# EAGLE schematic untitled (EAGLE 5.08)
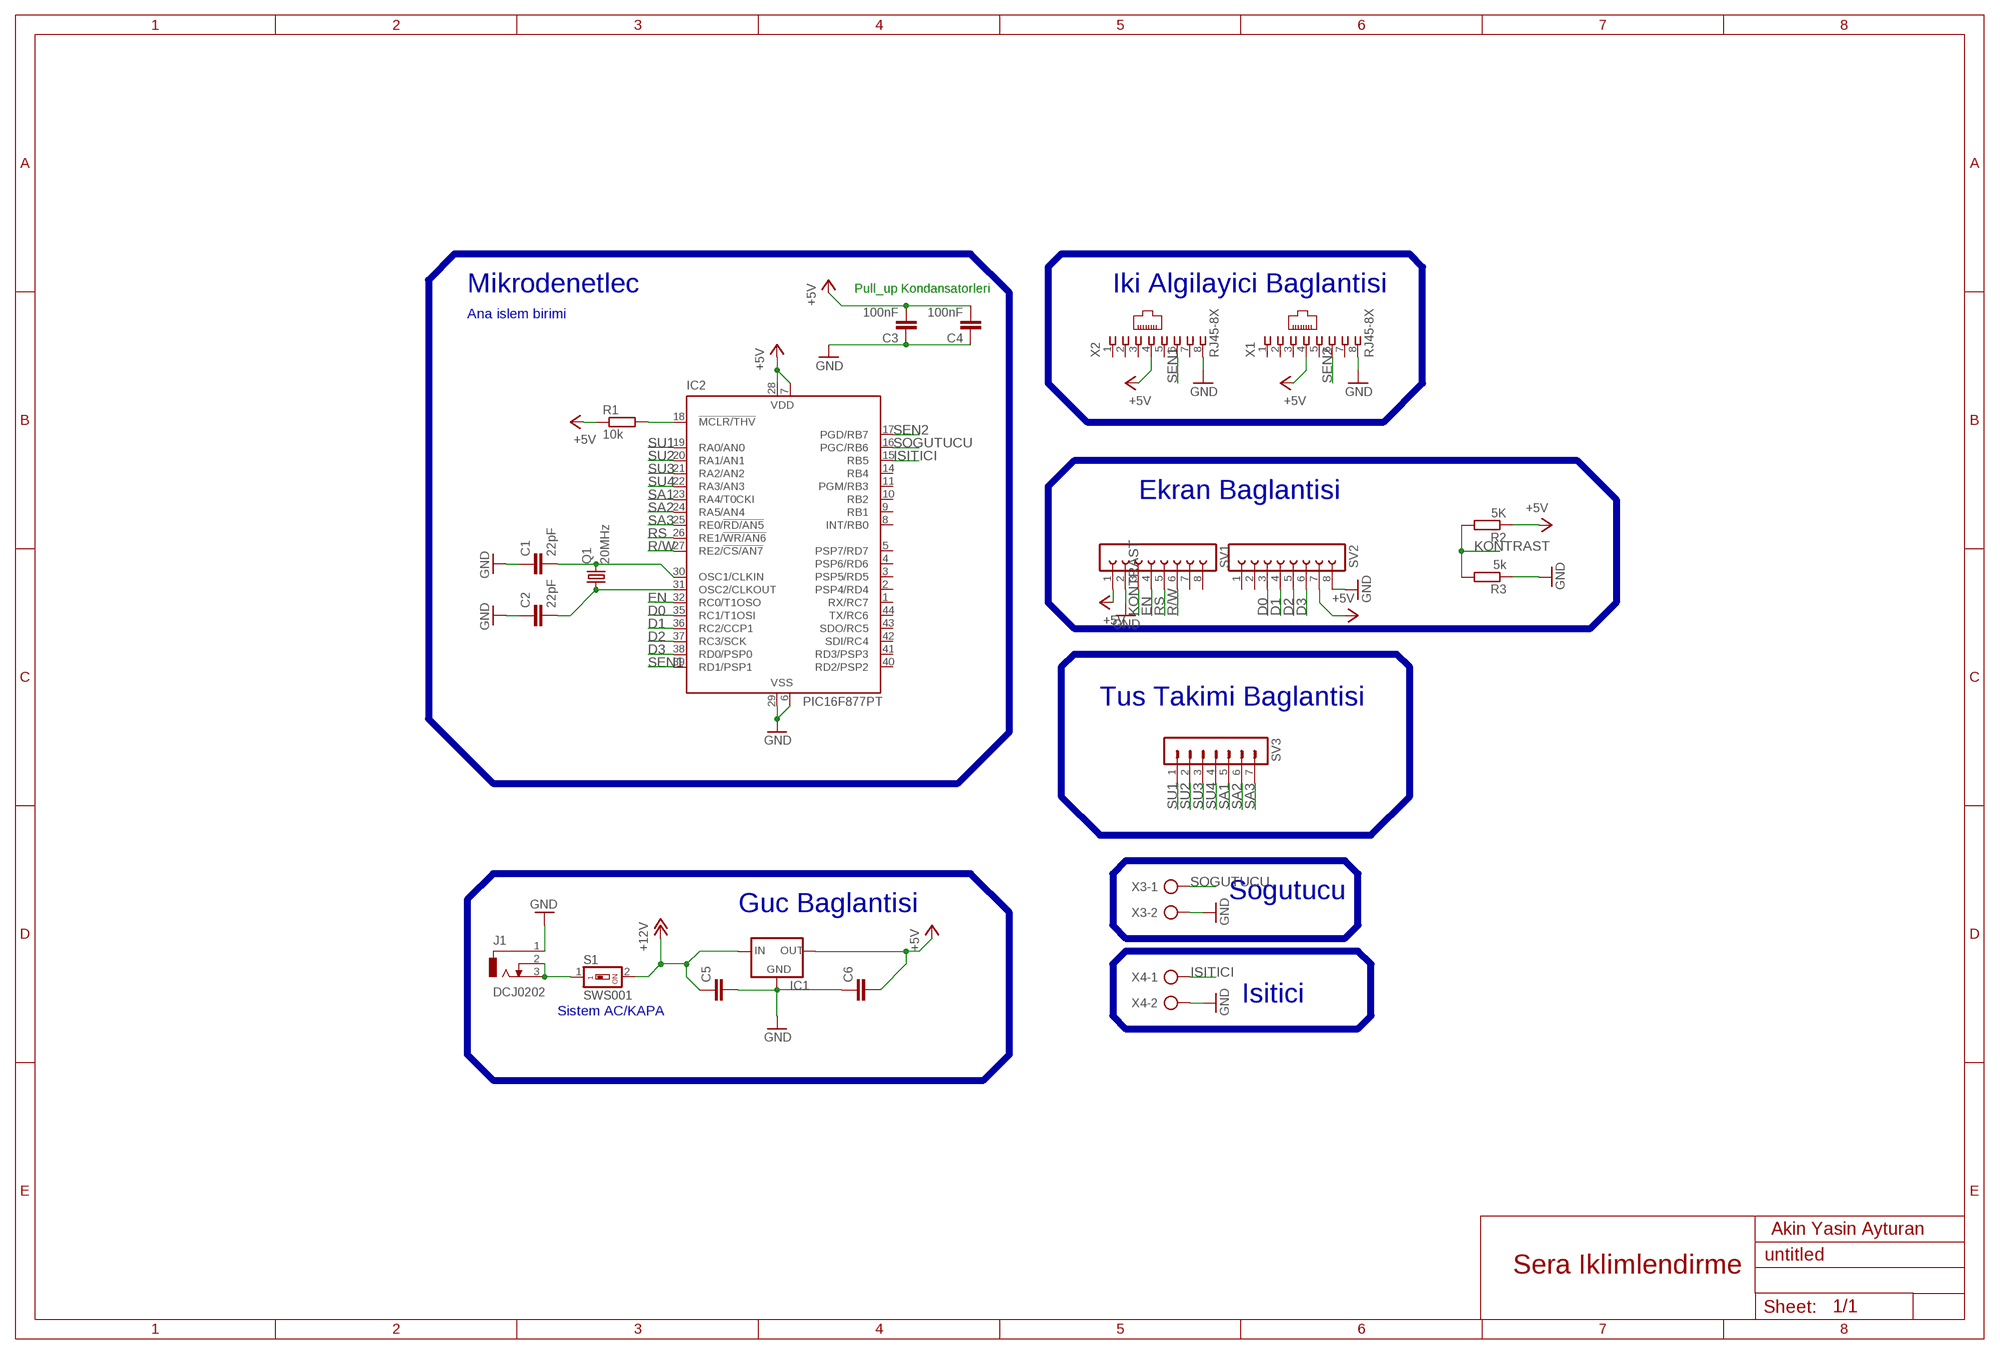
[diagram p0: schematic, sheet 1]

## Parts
C1  22pF  C-EUC0402  [C0402]
C2  22pF  C-EUC0402  [C0402]
C3  100nF  C-EUC1206  [C1206]
C4  100nF  C-EUC1206  [C1206]
C5  C-EU050-045X075  [C050-045X075]
C6  C-EU050-045X075  [C050-045X075]
IC1  78LXX  [78LXX]
IC2  PIC16F877PT  [TQFP44]
J1  DCJ0202  [DCJ0202]
Q1  20MHz  CRYSTALSM49  [SM49]
R1  10k  R-EU_M1206  [M1206]
R2  5K  R-EU_M1206  [M1206]
R3  5k  R-EU_M1206  [M1206]
S1  SWS001  [SMS-001]
SV1  FE08-1  [FE08]
SV2  FE08-1  [FE08]
SV3  MA07-1  [MA07-1]
X1  RJ45-8X  [RJ45-NO-SHIELD]
X2  RJ45-8X  [RJ45-NO-SHIELD]
X3  AK300/2  [AK300/2]
X4  AK300/2  [AK300/2]

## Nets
+5V: C3.2 C4.2 C6.2 IC1.OUT IC2.7(VDD) IC2.28(VDD) R1.1 R2.1 SV1.1 SV2.7 X1.4 X2.4
+12V: C5.1 IC1.IN S1.2
D0: IC2.35(RC1/T1OSI) SV2.3
D1: IC2.36(RC2/CCP1) SV2.4
D2: IC2.37(RC3/SCK) SV2.5
D3: IC2.38(RD0/PSP0) SV2.6
EN: IC2.32(RC0/T1OSO) SV1.4
GND: C1.1 C2.1 C3.1 C4.1 C5.2 C6.1 IC1.GND IC2.6(VSS) IC2.29(VSS) J1.1 R3.1 SV1.2 SV2.8 X1.8 X2.8 X3.2 X4.2
ISITICI: IC2.15(RB5) X4.1
KONTRAST: R2.2 R3.2 SV1.3
N$1: IC2.18(!MCLR/THV) R1.2
N$2: C1.2 IC2.30(OSC1/CLKIN) Q1.2
N$3: C2.2 IC2.31(OSC2/CLKOUT) Q1.1
N$4: J1.2 J1.3 S1.1
R/W: IC2.27(RE2/!CS/AN7) SV1.6
RS: IC2.26(RE1/!WR/AN6) SV1.5
SA1: IC2.23(RA4/T0CKI) SV3.5
SA2: IC2.24(RA5/AN4) SV3.6
SA3: IC2.25(RE0/!RD/AN5) SV3.7
SEN1: IC2.39(RD1/PSP1) X2.6
SEN2: IC2.17(PGD/RB7) X1.6
SOGUTUCU: IC2.16(PGC/RB6) X3.1
SU1: IC2.19(RA0/AN0) SV3.1
SU2: IC2.20(RA1/AN1) SV3.2
SU3: IC2.21(RA2/AN2) SV3.3
SU4: IC2.22(RA3/AN3) SV3.4
Unconnected: IC2.1(RX/RC7) IC2.2(PSP4/RD4) IC2.3(PSP5/RD5) IC2.4(PSP6/RD6) IC2.5(PSP7/RD7) IC2.8(INT/RB0) IC2.9(RB1) IC2.10(RB2) IC2.11(PGM/RB3) IC2.14(RB4) IC2.40(RD2/PSP2) IC2.41(RD3/PSP3) IC2.42(SDI/RC4) IC2.43(SDO/RC5) IC2.44(TX/RC6) SV1.7 SV1.8 SV2.1 SV2.2 X1.1 X1.2 X1.3 X1.5 X1.7 X2.1 X2.2 X2.3 X2.5 X2.7

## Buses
B$2
B$3
B$4
B$5
B$6
B$7
B$1

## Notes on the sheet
- Mikrodenetlec | Pull_up Kondansatorleri | Iki Algilayici Baglantisi
- Ana islem birimi
- Ekran Baglantisi
- Tus Takimi Baglantisi
- Sogutucu
- Guc Baglantisi
- Isitici
- Sistem AC/KAPA
- Akin Yasin Ayturan
- Sera Iklimlendirme

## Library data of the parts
C1-C6 = resistor:C-EU: CAPACITOR, European symbol
IC1 = v-reg:78LXX: VOLTAGE REGULATOR
IC2 = microchip:PIC16F87*: MICROCONTROLLER
J1 = con-jack:DCJ0202: DC POWER JACK Source: DCJ0202.pdf
Q1 = crystal:CRYSTAL: CRYSTAL
R1-R3 = resistor:R-EU_: RESISTOR, European symbol
S1 = smd-special:SWS001: SMD Dip Switch 1 pol.
SV1 SV2 = con-lsta:FE08-1: FEMALE HEADER
SV3 = con-lstb:MA07-1: PIN HEADER
X1 X2 = con-tycoelectronics:RJ45: CORCOM Modular RJ Jacks No Shield Source: www.tycoelectronics.com .. ENG_DS_1654001_1099_RJ_L_0507.pdf
X3 X4 = con-ptr500:AK300/2: CONNECTOR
